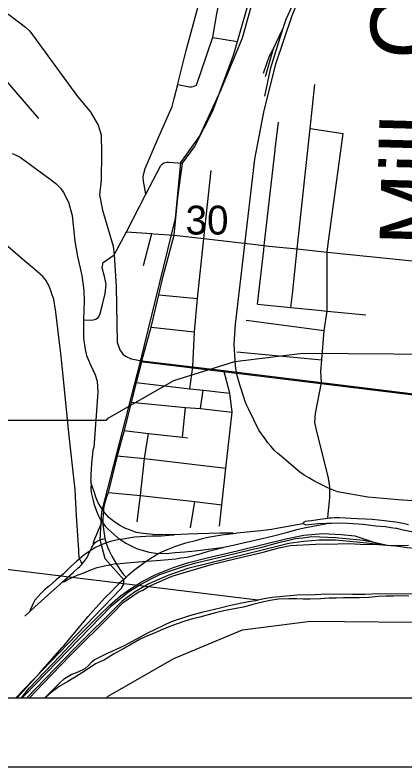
# Model space of a CAD drawing. Extents: x -8.2 to 38.5, y -0.1 to 21.9.
# Drawn here: x 4.691 to 5.256, y 13.864 to 14.955 of the extents above; entities that cross this region are included whole.
import ezdxf

# ---------------------------------------------------------------- set-up
doc = ezdxf.new("R2010")
doc.units = 0
for name, color, linetype in [('Default', 7, 'Continuous'), ('GM_X_Adjacent_County_Text', 7, 'Continuous'), ('GM_X_Airport_Location_Class_1', 7, 'Continuous'), ('GM_X_Airport_Location_Class_3', 7, 'Continuous'), ('GM_X_County_Road_Text', 7, 'Continuous'), ('GM_X_Interstate_Location', 7, 'Continuous'), ('GM_X_Minor_River_Text', 7, 'Continuous'), ('GM_X_Section', 7, 'Continuous'), ('GM_X_Township', 7, 'Continuous'), ('GM_X_Township_ROW', 7, 'Continuous'), ('GM_X_Township_Subdivision_Text', 7, 'Continuous'), ('GM_X_Township_Text', 7, 'Continuous'), ('GM_X_US_Location', 7, 'Continuous')]:
    doc.layers.add(name, color=color, linetype=linetype)

msp = doc.modelspace()

# ---------------------------------------------------------------- linework, layer by layer
at = {"layer": 'Default'}
for points in [[(3.4133, 14.3673), (4.8235, 14.3673), (4.826, 14.3701), (4.9209, 14.4247), (5.0093, 14.4526), (5.1079, 14.4647), (5.3056, 14.4632), (5.5006, 14.42), (5.5963, 14.3828), (5.6234, 14.3673), (7.7858, 14.3673), (7.8175, 14.393), (7.9342, 14.5067), (8.01, 14.5807), (8.079, 14.6766), (8.1908, 14.868), (8.2378, 14.965), (8.3715, 15.1656), (8.4492, 15.2533), (8.7111, 15.5504), (8.81, 15.6288), (8.9073, 15.6804), (8.9634, 15.7165), (8.9634, 21.1673)], [(3.4095, 13.9645), (4.8235, 13.9645), (4.826, 13.9672), (4.9209, 14.0218), (5.0207, 14.0635), (5.1194, 14.0757), (5.317, 14.0741), (5.5121, 14.0309), (5.6077, 13.9937), (5.659, 13.9645), (7.7815, 13.9645)]]:
    msp.add_lwpolyline(points, dxfattribs=at)
msp.add_lwpolyline([(4.3924, 13.9645), (4.7341, 13.9645), (4.7553, 13.9861), (4.7627, 13.9928), (4.7723, 13.9983), (4.7822, 14.0026), (4.7922, 14.0073), (4.7968, 14.011), (4.8026, 14.0173), (4.8057, 14.0198), (4.8218, 14.0278), (4.8494, 14.0408), (4.8835, 14.059), (4.9176, 14.0756), (4.9443, 14.0841), (4.9634, 14.0893), (4.9881, 14.0952), (5.003, 14.099), (5.0293, 14.1045), (5.0429, 14.1065), (4.4166, 14.1829)], close=True, dxfattribs=at)
at = {"layer": 'GM_X_Adjacent_County_Text'}
msp.add_lwpolyline([(5.5208, 15.0744), (5.4096, 14.1041), (5.3356, 14.1149), (5.2909, 14.1152), (5.217, 14.1154), (5.198, 14.1143), (5.1802, 14.1143), (5.1428, 14.1148), (5.1257, 14.114), (5.0999, 14.1135), (5.0844, 14.1123), (5.0635, 14.1102), (5.0544, 14.1088), (5.0429, 14.1065), (4.4166, 14.1829), (4.5212, 15.1931)], close=True, dxfattribs=at)
at = {"layer": 'GM_X_Airport_Location_Class_1'}
for p, q in [((5.1432, 14.2181), (5.1497, 14.2182)), ((5.2431, 14.2107), (5.244, 14.2106)), ((5.244, 14.2106), (5.2494, 14.2094)), ((5.2494, 14.2094), (5.2512, 14.209))]:
    msp.add_line(p, q, dxfattribs=at)
for points in [[(4.6497, 14.9791), (4.6875, 14.9514), (4.7057, 14.9371), (4.7124, 14.9313), (4.7815, 14.8367), (4.7999, 14.8149), (4.8111, 14.7952), (4.8155, 14.7812), (4.8161, 14.755), (4.8154, 14.7155), (4.8132, 14.694), (4.8175, 14.6716), (4.8331, 14.6197), (4.8347, 14.6071), (4.8372, 14.5609), (4.8388, 14.4806), (4.8425, 14.4695), (4.8471, 14.4631), (4.8511, 14.46), (4.8592, 14.4561), (4.8744, 14.4535)], [(4.8744, 14.4535), (4.8665, 14.4221), (4.8592, 14.3936), (4.849, 14.3521), (4.8386, 14.3156), (4.8258, 14.2626), (4.8225, 14.2526), (4.822, 14.2509)], [(4.822, 14.2509), (4.8214, 14.2492), (4.8204, 14.2459), (4.8194, 14.2418), (4.8188, 14.238), (4.8188, 14.2349), (4.8183, 14.2308), (4.8181, 14.2233), (4.8181, 14.2161), (4.8188, 14.2091), (4.8198, 14.2023), (4.821, 14.1959), (4.8229, 14.1888), (4.8253, 14.1821), (4.8271, 14.1777), (4.8311, 14.1701), (4.838, 14.1586), (4.8429, 14.151), (4.8475, 14.1441), (4.8517, 14.1397)], [(5.0072, 14.2031), (5.013, 14.2039), (5.0468, 14.2073), (5.055, 14.2081), (5.0626, 14.2093), (5.073, 14.211), (5.0814, 14.2128), (5.0893, 14.214), (5.0971, 14.2157), (5.1084, 14.2175)], [(5.1084, 14.2175), (5.1085, 14.2175), (5.1103, 14.2164), (5.1125, 14.2157), (5.1212, 14.2166), (5.1302, 14.2175), (5.1432, 14.2181)], [(5.1497, 14.2182), (5.1599, 14.2184), (5.1733, 14.2182), (5.1954, 14.2164), (5.2138, 14.2143), (5.2277, 14.2131), (5.2356, 14.2117), (5.2431, 14.2107)], [(5.2512, 14.209), (5.2656, 14.2059), (5.2851, 14.2005), (5.3093, 14.1911), (5.3709, 14.1655), (5.4001, 14.1549), (5.4129, 14.1514), (5.42, 14.1494), (5.4407, 14.1441), (5.4508, 14.1426)], [(4.8717, 14.1562), (4.8774, 14.1605), (4.8809, 14.1628), (4.8878, 14.1674), (4.8954, 14.1721), (4.8999, 14.1743), (4.9038, 14.1763), (4.9127, 14.1802), (4.9223, 14.1842), (4.9383, 14.1893), (4.9544, 14.1935), (4.9628, 14.1956)], [(4.9628, 14.1956), (4.9704, 14.1975), (4.9904, 14.2009), (5.0072, 14.2031)], [(4.8517, 14.1397), (4.8552, 14.143), (4.8643, 14.1506), (4.8717, 14.1562)]]:
    msp.add_lwpolyline(points, dxfattribs=at)
at = {"layer": 'GM_X_Airport_Location_Class_3'}
for p, q in [((5.1432, 14.2181), (5.1497, 14.2182)), ((5.2431, 14.2107), (5.244, 14.2106)), ((5.244, 14.2106), (5.2494, 14.2094)), ((5.2494, 14.2094), (5.2512, 14.209)), ((4.7613, 14.0399), (4.766, 14.0455)), ((4.7265, 14.0011), (4.7593, 14.0376)), ((4.7593, 14.0376), (4.7613, 14.0399)), ((4.6937, 13.9645), (4.7265, 14.0011))]:
    msp.add_line(p, q, dxfattribs=at)
for points in [[(5.0072, 14.2031), (5.013, 14.2039), (5.0468, 14.2073), (5.055, 14.2081), (5.0626, 14.2093), (5.073, 14.211), (5.0814, 14.2128), (5.0893, 14.214), (5.0971, 14.2157), (5.1084, 14.2175)], [(5.1084, 14.2175), (5.1085, 14.2175), (5.1103, 14.2164), (5.1125, 14.2157), (5.1212, 14.2166), (5.1302, 14.2175), (5.1432, 14.2181)], [(5.1085, 14.2175), (5.109, 14.2183), (5.1094, 14.2192), (5.1101, 14.22), (5.111, 14.2204), (5.1119, 14.2208), (5.116, 14.2213), (5.1206, 14.222), (5.1234, 14.2224), (5.1332, 14.2237), (5.1404, 14.2248), (5.1441, 14.2253), (5.1464, 14.2256), (5.1492, 14.2259)], [(5.1492, 14.2259), (5.1538, 14.2263), (5.1612, 14.2263), (5.1698, 14.2259), (5.1782, 14.2253), (5.1867, 14.2248), (5.1991, 14.2242), (5.2086, 14.2236), (5.2179, 14.2228), (5.2264, 14.2219), (5.2343, 14.2211), (5.2429, 14.2201), (5.2504, 14.2186), (5.2534, 14.2179)], [(5.1497, 14.2182), (5.1599, 14.2184), (5.1733, 14.2182), (5.1954, 14.2164), (5.2138, 14.2143), (5.2277, 14.2131), (5.2356, 14.2117), (5.2431, 14.2107)], [(5.2534, 14.2179), (5.2553, 14.2174), (5.2611, 14.2158)], [(5.2512, 14.209), (5.2656, 14.2059), (5.2851, 14.2005), (5.3093, 14.1911), (5.3709, 14.1655), (5.4001, 14.1549), (5.4129, 14.1514), (5.42, 14.1494), (5.4407, 14.1441), (5.4508, 14.1426)], [(4.8717, 14.1562), (4.8774, 14.1605), (4.8809, 14.1628), (4.8878, 14.1674), (4.8954, 14.1721), (4.8999, 14.1743), (4.9038, 14.1763), (4.9127, 14.1802), (4.9223, 14.1842), (4.9383, 14.1893), (4.9544, 14.1935), (4.9628, 14.1956)], [(4.9628, 14.1956), (4.9704, 14.1975), (4.9904, 14.2009), (5.0072, 14.2031)], [(4.8517, 14.1397), (4.8552, 14.143), (4.8643, 14.1506), (4.8717, 14.1562)], [(4.8408, 14.1297), (4.8429, 14.1319), (4.8482, 14.1364), (4.8517, 14.1397)], [(4.766, 14.0455), (4.7941, 14.0791), (4.797, 14.0825), (4.8042, 14.0907), (4.8165, 14.1047), (4.8219, 14.1107), (4.8296, 14.1181), (4.8367, 14.1255), (4.8408, 14.1297)]]:
    msp.add_lwpolyline(points, dxfattribs=at)
at = {"layer": 'GM_X_Interstate_Location'}
for points in [[(4.8009, 14.2754), (4.8008, 14.2675), (4.8017, 14.2604), (4.804, 14.2506), (4.8049, 14.2466), (4.8091, 14.2353), (4.8115, 14.2297), (4.8142, 14.224), (4.8161, 14.221), (4.8214, 14.2138), (4.8256, 14.2092), (4.83, 14.2052), (4.8397, 14.1966), (4.8514, 14.189), (4.8668, 14.1812), (4.8763, 14.1781), (4.8853, 14.176), (4.895, 14.1746), (4.9098, 14.1738), (4.9229, 14.1752), (4.9369, 14.1764), (4.9519, 14.1779), (4.9712, 14.1803), (4.9867, 14.1823), (4.9931, 14.1832)], [(4.9213, 14.2012), (4.8909, 14.2017), (4.8763, 14.2029), (4.8665, 14.2046), (4.858, 14.2076), (4.85, 14.2106), (4.8424, 14.2152), (4.834, 14.2206), (4.8269, 14.2264), (4.8207, 14.2336), (4.8156, 14.2407), (4.8113, 14.2474), (4.8079, 14.2555), (4.8059, 14.2624), (4.8033, 14.2703), (4.8009, 14.2754)], [(4.8181, 14.2233), (4.806, 14.1949), (4.8042, 14.1895), (4.8039, 14.1861)], [(4.9931, 14.1832), (4.9931, 14.1832), (5.0068, 14.1863), (5.0214, 14.1894), (5.0493, 14.1956), (5.0653, 14.1997), (5.0845, 14.2044), (5.0993, 14.2089), (5.1099, 14.211), (5.1301, 14.2153), (5.1407, 14.2169), (5.1423, 14.2176), (5.1432, 14.2181)], [(4.9213, 14.2012), (4.9204, 14.2008), (4.9192, 14.2004), (4.9029, 14.1993), (4.8895, 14.199), (4.8802, 14.1985), (4.8723, 14.198), (4.8642, 14.1975), (4.8557, 14.1964), (4.847, 14.195), (4.8371, 14.1932), (4.829, 14.1916), (4.8207, 14.1885), (4.8139, 14.1857), (4.8075, 14.1829), (4.8022, 14.1791), (4.7925, 14.173), (4.7878, 14.1692), (4.7799, 14.1623), (4.7715, 14.1552), (4.7608, 14.1446), (4.7505, 14.1357), (4.7408, 14.1273), (4.7337, 14.1211), (4.7286, 14.1165), (4.7232, 14.1109), (4.7196, 14.1061), (4.7166, 14.1007), (4.7117, 14.0894)], [(5.0072, 14.2031), (5.0069, 14.2032), (5.0066, 14.2033), (5.0044, 14.2033), (4.9884, 14.2034), (4.9557, 14.2027), (4.9414, 14.2019), (4.9213, 14.2012)], [(4.7596, 14.1328), (4.7609, 14.133), (4.7626, 14.1335), (4.7665, 14.1356), (4.7801, 14.1421), (4.7904, 14.1461), (4.7972, 14.149), (4.8032, 14.1513), (4.8098, 14.1535), (4.8159, 14.1549), (4.8228, 14.1566), (4.8289, 14.1577), (4.8346, 14.1588), (4.843, 14.1597), (4.8527, 14.1605), (4.8692, 14.1618), (4.9015, 14.1645), (4.9241, 14.1664), (4.931, 14.1676), (4.9402, 14.1687), (4.9499, 14.171), (4.9606, 14.1738), (4.9714, 14.1775), (4.981, 14.1799), (4.9922, 14.1825), (4.9928, 14.1828)]]:
    msp.add_lwpolyline(points, dxfattribs=at)
at = {"layer": 'GM_X_Section'}
msp.add_lwpolyline([(2.1634, 13.9645), (4.8235, 13.9645), (4.826, 13.9672), (4.9209, 14.0218), (5.0207, 14.0635), (5.1194, 14.0757), (5.317, 14.0741), (5.5121, 14.0309), (5.6077, 13.9937), (5.659, 13.9645), (7.7815, 13.9645)], dxfattribs=at)
at = {"layer": 'GM_X_Township'}
for p, q in [((2.1634, 13.9645), (8.9634, 13.9645)), ((2.0634, 13.8645), (9.0634, 13.8645))]:
    msp.add_line(p, q, dxfattribs=at)
at = {"layer": 'GM_X_Township_ROW'}
msp.add_lwpolyline([(5.262, 14.1123), (5.2507, 14.1126), (5.2396, 14.1121), (5.229, 14.112), (5.2176, 14.1115), (5.2036, 14.1104), (5.1899, 14.1099), (5.177, 14.1099), (5.1671, 14.1098), (5.1565, 14.1093), (5.1462, 14.1091), (5.1337, 14.1083), (5.1185, 14.1079), (5.1086, 14.1078), (5.0988, 14.1084), (5.0878, 14.1083), (5.073, 14.1076), (5.0608, 14.106), (5.0471, 14.1029), (5.0356, 14.0998), (5.0238, 14.0967), (5.0089, 14.0936), (4.9952, 14.0913), (4.9814, 14.0879), (4.9707, 14.0851), (4.9585, 14.0816), (4.9482, 14.0792), (4.9356, 14.0754), (4.9256, 14.0718), (4.9153, 14.0679), (4.9046, 14.0636), (4.8927, 14.0586), (4.8819, 14.0543), (4.872, 14.0496), (4.8573, 14.0413), (4.8473, 14.0358), (4.8335, 14.0278), (4.8204, 14.0198), (4.8073, 14.0141), (4.7923, 14.0038), (4.7792, 13.9954), (4.7672, 13.9885), (4.7545, 13.9812), (4.7433, 13.9724), (4.7344, 13.9645)], dxfattribs=at)
at = {"layer": 'GM_X_Township_Subdivision_Text'}
for p, q in [((4.9775, 14.9223), (5.0132, 14.9166)), ((5.1186, 14.7902), (5.1666, 14.7831)), ((4.8522, 14.6406), (4.8889, 14.6379)), ((4.8769, 14.5917), (4.8889, 14.6379)), ((4.8991, 14.5492), (4.9551, 14.5438)), ((5.0257, 14.5122), (5.1392, 14.4974)), ((4.8881, 14.5023), (4.951, 14.4954)), ((5.0122, 14.4663), (5.1354, 14.4549)), ((4.9595, 14.3842), (4.9635, 14.4106)), ((4.9338, 14.3428), (4.9377, 14.3858)), ((4.9451, 14.2111), (4.9513, 14.2495))]:
    msp.add_line(p, q, dxfattribs=at)
for points in [[(4.8806, 14.6948), (4.8771, 14.7141), (4.8766, 14.7199), (4.8774, 14.7248), (4.8795, 14.732), (4.8985, 14.7761), (4.9185, 14.8222), (4.9217, 14.8339), (4.9266, 14.8539), (4.9274, 14.8571), (4.9387, 14.9033), (4.9568, 14.9693), (4.9606, 14.9886), (4.9678, 15.0457)], [(4.954, 14.8533), (4.9773, 14.9211), (4.9775, 14.9223), (4.9781, 14.9257), (4.9834, 14.9563), (4.9872, 14.9755), (4.9942, 15.0198)], [(4.6497, 14.8913), (4.7249, 14.8046)], [(4.9266, 14.8539), (4.9437, 14.8505), (4.9465, 14.8505), (4.949, 14.8509), (4.954, 14.8533)], [(5.0908, 14.5307), (5.0929, 14.5502), (5.0999, 14.6156), (5.1186, 14.7902), (5.1256, 14.8538)], [(5.068, 14.7595), (5.0681, 14.7604), (5.0726, 14.7996)], [(5.1432, 14.6016), (5.1433, 14.6111), (5.1448, 14.6229), (5.1666, 14.7831)], [(5.0424, 14.5354), (5.0514, 14.6137), (5.0522, 14.6206), (5.067, 14.7507), (5.068, 14.7595)], [(4.8347, 14.6071), (4.8522, 14.6406), (4.8806, 14.6948), (4.9023, 14.7365), (4.9043, 14.7386), (4.9065, 14.7405), (4.9107, 14.7415), (4.9134, 14.7415), (4.9338, 14.7399)], [(4.9441, 14.4128), (4.9487, 14.4446), (4.951, 14.4954), (4.9551, 14.5438), (4.9644, 14.6306), (4.9749, 14.7292)], [(4.8889, 14.6379), (4.8918, 14.6377), (4.9214, 14.6356)], [(5.1441, 14.2253), (5.1449, 14.2315), (5.1473, 14.2547), (5.1473, 14.2707), (5.1455, 14.2834), (5.1275, 14.355), (5.1255, 14.364), (5.1266, 14.3768), (5.1349, 14.4219), (5.1342, 14.4385), (5.1354, 14.4549), (5.1392, 14.4974), (5.1432, 14.5255), (5.1432, 14.6016)], [(5.0424, 14.5354), (5.0908, 14.5307), (5.1307, 14.5267), (5.1432, 14.5255), (5.1994, 14.5199)], [(4.9873, 14.2137), (4.9906, 14.2447), (4.9966, 14.2976), (5.0058, 14.3789), (5.0021, 14.4065), (4.9935, 14.4393)], [(4.8665, 14.4221), (4.9441, 14.4128), (4.9635, 14.4106), (5.0021, 14.4065)], [(4.8592, 14.3936), (4.9377, 14.3858), (4.9595, 14.3842), (5.0058, 14.3789)], [(4.849, 14.3521), (4.8843, 14.348), (4.9338, 14.3428), (4.9409, 14.3417)], [(4.8678, 14.2198), (4.8725, 14.2581), (4.8786, 14.3116), (4.8843, 14.348)], [(4.8386, 14.3156), (4.8786, 14.3116), (4.9966, 14.2976)], [(4.8258, 14.2626), (4.8725, 14.2581), (4.9513, 14.2495), (4.9906, 14.2447)]]:
    msp.add_lwpolyline(points, dxfattribs=at)
at = {"layer": 'GM_X_Township_Text'}
for points in [[(4.8744, 14.4535), (4.8881, 14.5023), (4.8991, 14.5492), (4.9053, 14.576), (4.9214, 14.6356), (4.9267, 14.6901), (4.9338, 14.7399), (4.9512, 14.7638), (4.9774, 14.8158), (5.0074, 14.8965), (5.0132, 14.9166), (5.0473, 15.0347), (5.0513, 15.0503), (5.0622, 15.0931), (5.0666, 15.1002), (5.0852, 15.1262), (5.113, 15.164), (5.251, 15.3515), (5.3071, 15.4277), (5.3298, 15.4642), (5.378, 15.5444), (5.4003, 15.5859), (5.4126, 15.6094)], [(4.6865, 14.7539), (4.6934, 14.7511), (4.6983, 14.7485), (4.7416, 14.7166), (4.7498, 14.7104), (4.7565, 14.7038), (4.7611, 14.6972), (4.7684, 14.6832), (4.7734, 14.6639), (4.7774, 14.627), (4.7812, 14.6048), (4.7874, 14.5773), (4.7904, 14.5552), (4.791, 14.5399), (4.7899, 14.5128), (4.7902, 14.4863), (4.7923, 14.4698), (4.7945, 14.4613), (4.8004, 14.4476), (4.807, 14.4331), (4.8099, 14.4237), (4.811, 14.4079), (4.8049, 14.3278), (4.8037, 14.3237), (4.803, 14.3182), (4.8024, 14.3141), (4.8016, 14.3042), (4.8011, 14.2964), (4.8008, 14.2892), (4.8005, 14.2825), (4.8004, 14.281), (4.8005, 14.2795), (4.8006, 14.2782), (4.8007, 14.2766), (4.8009, 14.2754)], [(4.7051, 14.598), (4.6703, 14.6277), (4.6379, 14.6571), (4.6235, 14.6733)], [(4.9214, 14.6356), (4.9644, 14.6306), (5.0522, 14.6206), (5.0589, 14.6198), (5.0999, 14.6156), (5.1433, 14.6111), (5.4244, 14.5822), (5.5998, 14.5677), (5.6698, 14.5606), (5.6904, 14.5571), (5.6934, 14.5565)], [(4.7899, 14.5128), (4.8023, 14.5121), (4.8077, 14.5137), (4.8116, 14.5168), (4.8143, 14.5222), (4.8176, 14.5349), (4.8216, 14.5509), (4.8228, 14.5644), (4.8207, 14.5756), (4.8172, 14.588), (4.8187, 14.596), (4.8347, 14.6071)], [(4.7558, 14.4757), (4.7499, 14.5238), (4.7472, 14.5424), (4.7404, 14.5615), (4.7353, 14.5704), (4.7309, 14.5758), (4.7194, 14.5858), (4.7051, 14.598)], [(4.7883, 14.1589), (4.7875, 14.1605), (4.7867, 14.1618), (4.7856, 14.164), (4.7852, 14.1648), (4.7848, 14.1656), (4.7842, 14.1671), (4.7839, 14.168), (4.7837, 14.1687), (4.7835, 14.1704), (4.7833, 14.1745), (4.7832, 14.1786), (4.7819, 14.1999), (4.7801, 14.2284), (4.778, 14.2662), (4.7691, 14.3446), (4.7584, 14.4505), (4.7573, 14.464), (4.7558, 14.4757)], [(4.8744, 14.4535), (4.9487, 14.4446), (4.9935, 14.4393), (5.1349, 14.4219)], [(5.1349, 14.4219), (5.5352, 14.3727), (5.5787, 14.3671)], [(4.7051, 14.0833), (4.7117, 14.0894), (4.7196, 14.0967), (4.7566, 14.1301), (4.7596, 14.1328), (4.7749, 14.1464), (4.7819, 14.1528), (4.7846, 14.1553), (4.7871, 14.1577), (4.7883, 14.1589), (4.7907, 14.1619), (4.7923, 14.1642), (4.7938, 14.1663), (4.7951, 14.1684), (4.7967, 14.1716), (4.7989, 14.1757), (4.8005, 14.1791), (4.8023, 14.1831), (4.8039, 14.1861), (4.8043, 14.1869), (4.8064, 14.1893), (4.8089, 14.1915), (4.8119, 14.1928), (4.8142, 14.1936), (4.8171, 14.1948), (4.821, 14.1959)]]:
    msp.add_lwpolyline(points, dxfattribs=at)
at = {"layer": 'GM_X_US_Location'}
for p, q in [((5.0656, 14.906), (5.0788, 14.9336)), ((5.0537, 14.8656), (5.0656, 14.906)), ((4.8726, 14.4523), (5.0081, 14.4361))]:
    msp.add_line(p, q, dxfattribs=at)
for points in [[(4.8726, 14.4523), (4.9232, 14.6599), (4.9312, 14.7407), (4.9581, 14.7787), (4.9894, 14.8466), (5.0205, 14.9215), (5.0456, 15.0123), (5.0661, 15.0863), (5.0847, 15.1193), (5.258, 15.3581), (5.3154, 15.438), (5.3904, 15.5758), (5.4018, 15.5913)], [(5.3369, 14.2452), (5.2469, 14.2516), (5.2023, 14.2555), (5.1583, 14.2636), (5.1512, 14.2662), (5.1442, 14.2692), (5.1374, 14.2725), (5.124, 14.2795), (5.1169, 14.2835), (5.11, 14.2878), (5.1034, 14.2925), (5.0971, 14.2975), (5.077, 14.3144), (5.0717, 14.3191), (5.0667, 14.324), (5.0619, 14.3292), (5.0574, 14.3346), (5.0532, 14.3402), (5.0444, 14.3527), (5.0297, 14.3827), (5.027, 14.3886), (5.0246, 14.3945), (5.0225, 14.4006), (5.0167, 14.4185), (5.0147, 14.4253), (5.013, 14.4322), (5.0116, 14.4393), (5.0106, 14.4463), (5.01, 14.4535), (5.0084, 14.4775), (5.0102, 14.5066), (5.0171, 14.5638), (5.0385, 14.746), (5.0516, 14.8138), (5.0691, 14.8839), (5.0925, 14.9542), (5.1173, 15.0148)], [(5.1173, 15.0148), (5.0949, 14.9736), (5.0836, 14.9482), (5.0788, 14.9336)], [(5.0788, 14.9336), (5.073, 14.9154), (5.0606, 14.8764), (5.0523, 14.837)], [(5.0656, 14.906), (5.0594, 14.8952), (5.0505, 14.87)], [(4.6919, 13.9645), (4.8441, 14.1227), (4.8449, 14.1237), (4.8483, 14.1294), (4.8487, 14.1357), (4.8215, 14.1661), (4.814, 14.194), (4.8166, 14.2344), (4.8726, 14.4523)], [(5.0081, 14.4361), (5.3395, 14.3953), (5.3523, 14.3938)], [(4.7003, 13.9645), (4.711, 13.9786), (4.7561, 14.0254), (4.7843, 14.0554), (4.8122, 14.0834), (4.8283, 14.099), (4.8439, 14.1124), (4.858, 14.1227), (4.8739, 14.1329), (4.8951, 14.1437), (4.9192, 14.1532), (4.9408, 14.1604), (4.9676, 14.1671), (5.0129, 14.178), (5.0836, 14.1954), (5.1094, 14.2006), (5.1369, 14.2028), (5.1634, 14.2017), (5.1833, 14.1995), (5.211, 14.1905)], [(4.701, 13.9645), (4.705, 13.9688), (4.8308, 14.098), (4.8552, 14.1183), (4.8729, 14.1292), (4.889, 14.1378), (4.9008, 14.1434), (4.9163, 14.149), (4.9348, 14.1553), (4.953, 14.1603), (4.9735, 14.1652), (4.9978, 14.171), (5.0157, 14.1752), (5.0336, 14.18), (5.0489, 14.1833), (5.0658, 14.1879), (5.077, 14.1907), (5.0876, 14.1933), (5.0976, 14.1955), (5.1079, 14.1967), (5.121, 14.1984), (5.1555, 14.197), (5.1962, 14.1934), (5.211, 14.1905), (5.231, 14.1861)], [(5.2191, 14.1871), (5.1859, 14.1906), (5.1554, 14.1933), (5.1317, 14.1933), (5.1095, 14.1913), (5.0877, 14.1883), (5.0296, 14.174), (4.9415, 14.1523), (4.9121, 14.1423), (4.8846, 14.1301), (4.8642, 14.1181), (4.8461, 14.1048), (4.7758, 14.0353), (4.7077, 13.9645)], [(4.7118, 13.9645), (4.7316, 13.9853), (4.7708, 14.0263), (4.8323, 14.0871), (4.8477, 14.1027), (4.8693, 14.1177), (4.8761, 14.121), (4.8845, 14.1263), (4.8965, 14.1316), (4.903, 14.1345), (4.9115, 14.1381), (4.92, 14.1416), (4.9393, 14.1474), (4.9771, 14.1584), (5.0279, 14.1705), (5.0504, 14.1758), (5.0733, 14.1821), (5.0896, 14.1854), (5.1269, 14.1877), (5.159, 14.1882), (5.1747, 14.1885), (5.1911, 14.1876), (5.2176, 14.1872), (5.2363, 14.1857), (5.2455, 14.1854), (5.2613, 14.1861)], [(5.2399, 14.1856), (5.2592, 14.1829), (5.2799, 14.1806), (5.2992, 14.1766), (5.314, 14.1718), (5.3419, 14.1605), (5.3642, 14.1524), (5.4001, 14.1404), (5.4271, 14.1324), (5.4739, 14.1162), (5.5084, 14.1046), (5.5432, 14.0902), (5.6819, 14.0453), (5.71, 14.0342), (5.739, 14.0197), (5.802, 13.9786)]]:
    msp.add_lwpolyline(points, dxfattribs=at)

# ---------------------------------------------------------------- texts
at = {"layer": 'GM_X_County_Road_Text'}
msp.add_text('30', height=0.04186, rotation=0, dxfattribs=at).set_placement((4.938, 14.6365))
at = {"layer": 'GM_X_Minor_River_Text'}
for s, rotation, p in [('Creek', 89.6595, (5.3009, 14.8908)), ('Mill', 88.4478, (5.3138, 14.6183))]:
    msp.add_text(s, height=0.09472, rotation=rotation, dxfattribs=at).set_placement(p)

doc.saveas('drawing.dxf')
